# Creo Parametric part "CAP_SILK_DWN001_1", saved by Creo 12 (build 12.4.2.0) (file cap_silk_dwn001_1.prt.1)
Units: Custom; MM, KILOGRAM, SECS

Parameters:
  PTC_WM_ITERATION = "0"
  PTC_WM_VERSION = "-.0"
  PTC_WM_LIFECYCLE_STATE = "In Work"
  PTC_WM_LIFECYCLE = "MO_CADDocument"
  PTC_WM_CREATED_BY = "Maximilian Roepper (Z0017RMS: MO)"
  PTC_WM_CREATED_ON = "18-Sep-26 11:36:42 AM"
  PTC_WM_MODIFIED_BY = "Maximilian Roepper (Z0017RMS: MO)"
  PTC_WM_MODIFIED_ON = "18-Sep-26 11:36:46 AM"
  PDMLINKNUMBER = "PDM000071455094"
  PTC_WM_NAME = "cap_silk_dwn001_1.prt"
  PTC_WM_NUMBER = "PDM000071455094"

Other parameters: WEIGHT, WEIGHT_FACTOR, WEIGHT_ADD, _MASS_TEMP, _DIFF_TEMP, MC_ERRORS, SUPPLIER

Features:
  1. coordinate system
  2. datum plane "PRT_YZ"
  3. datum plane "PRT_XY"
  4. datum plane "PRT_XZ"
  5. coordinate system
  6. datum axis
  7. datum axis
  8. datum axis
  9. coordinate system
  10. imported feature

Other named items: PRT, SIEMENS_MO, DRW_VIEW_ORG, PRT_X, PRT_Y, PRT_Z, CS0, ROUGH_GROB

Layers: 00_STD_CSYS-KSYS, 01_STD_PLANES-EBENEN, 02_STD_AXES-ACHSEN, 03_STD_CSYS-KSYS, 24_IMPORT_FEAT-IMPORT_KE

Surfaces: 10 plane, 4 cylinder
